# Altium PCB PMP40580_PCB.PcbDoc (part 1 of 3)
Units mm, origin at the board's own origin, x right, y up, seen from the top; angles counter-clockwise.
Board outline 215 x 165 mm, 2 copper layers (Top Layer, Bottom Layer), stack 1.575 mm thick; 235 components, 90 nets, 527 pads, 0 vias.
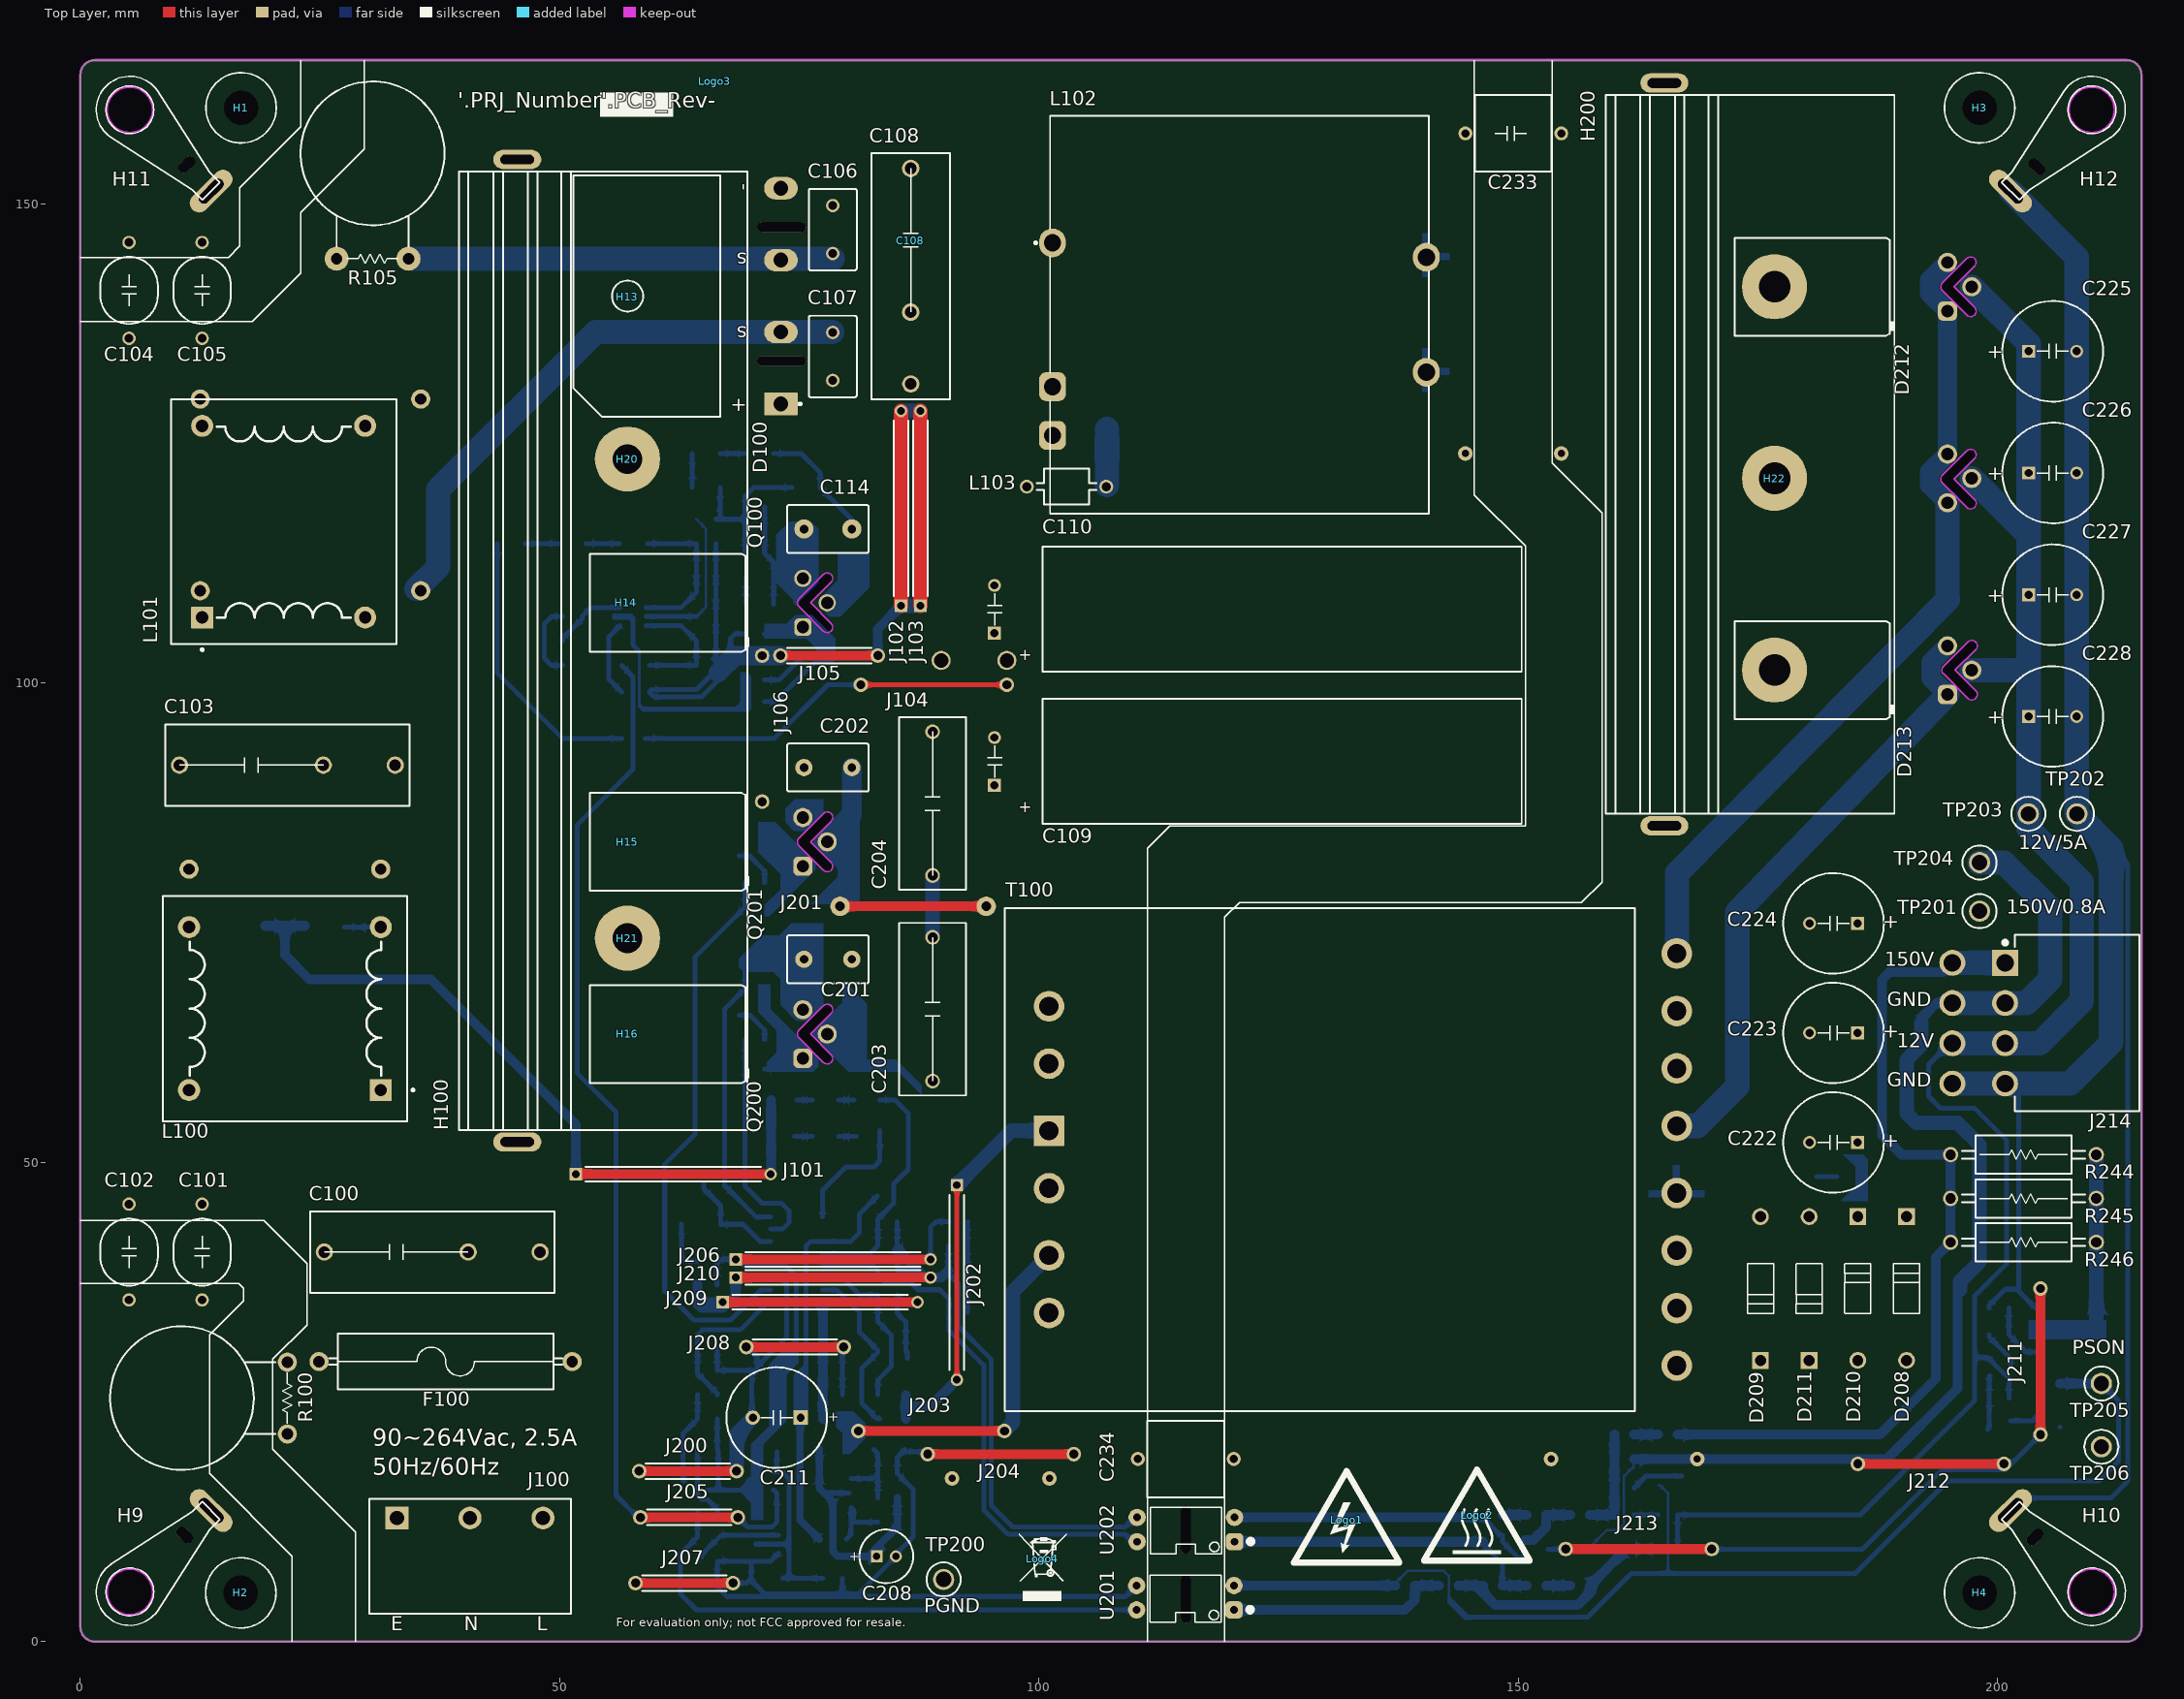
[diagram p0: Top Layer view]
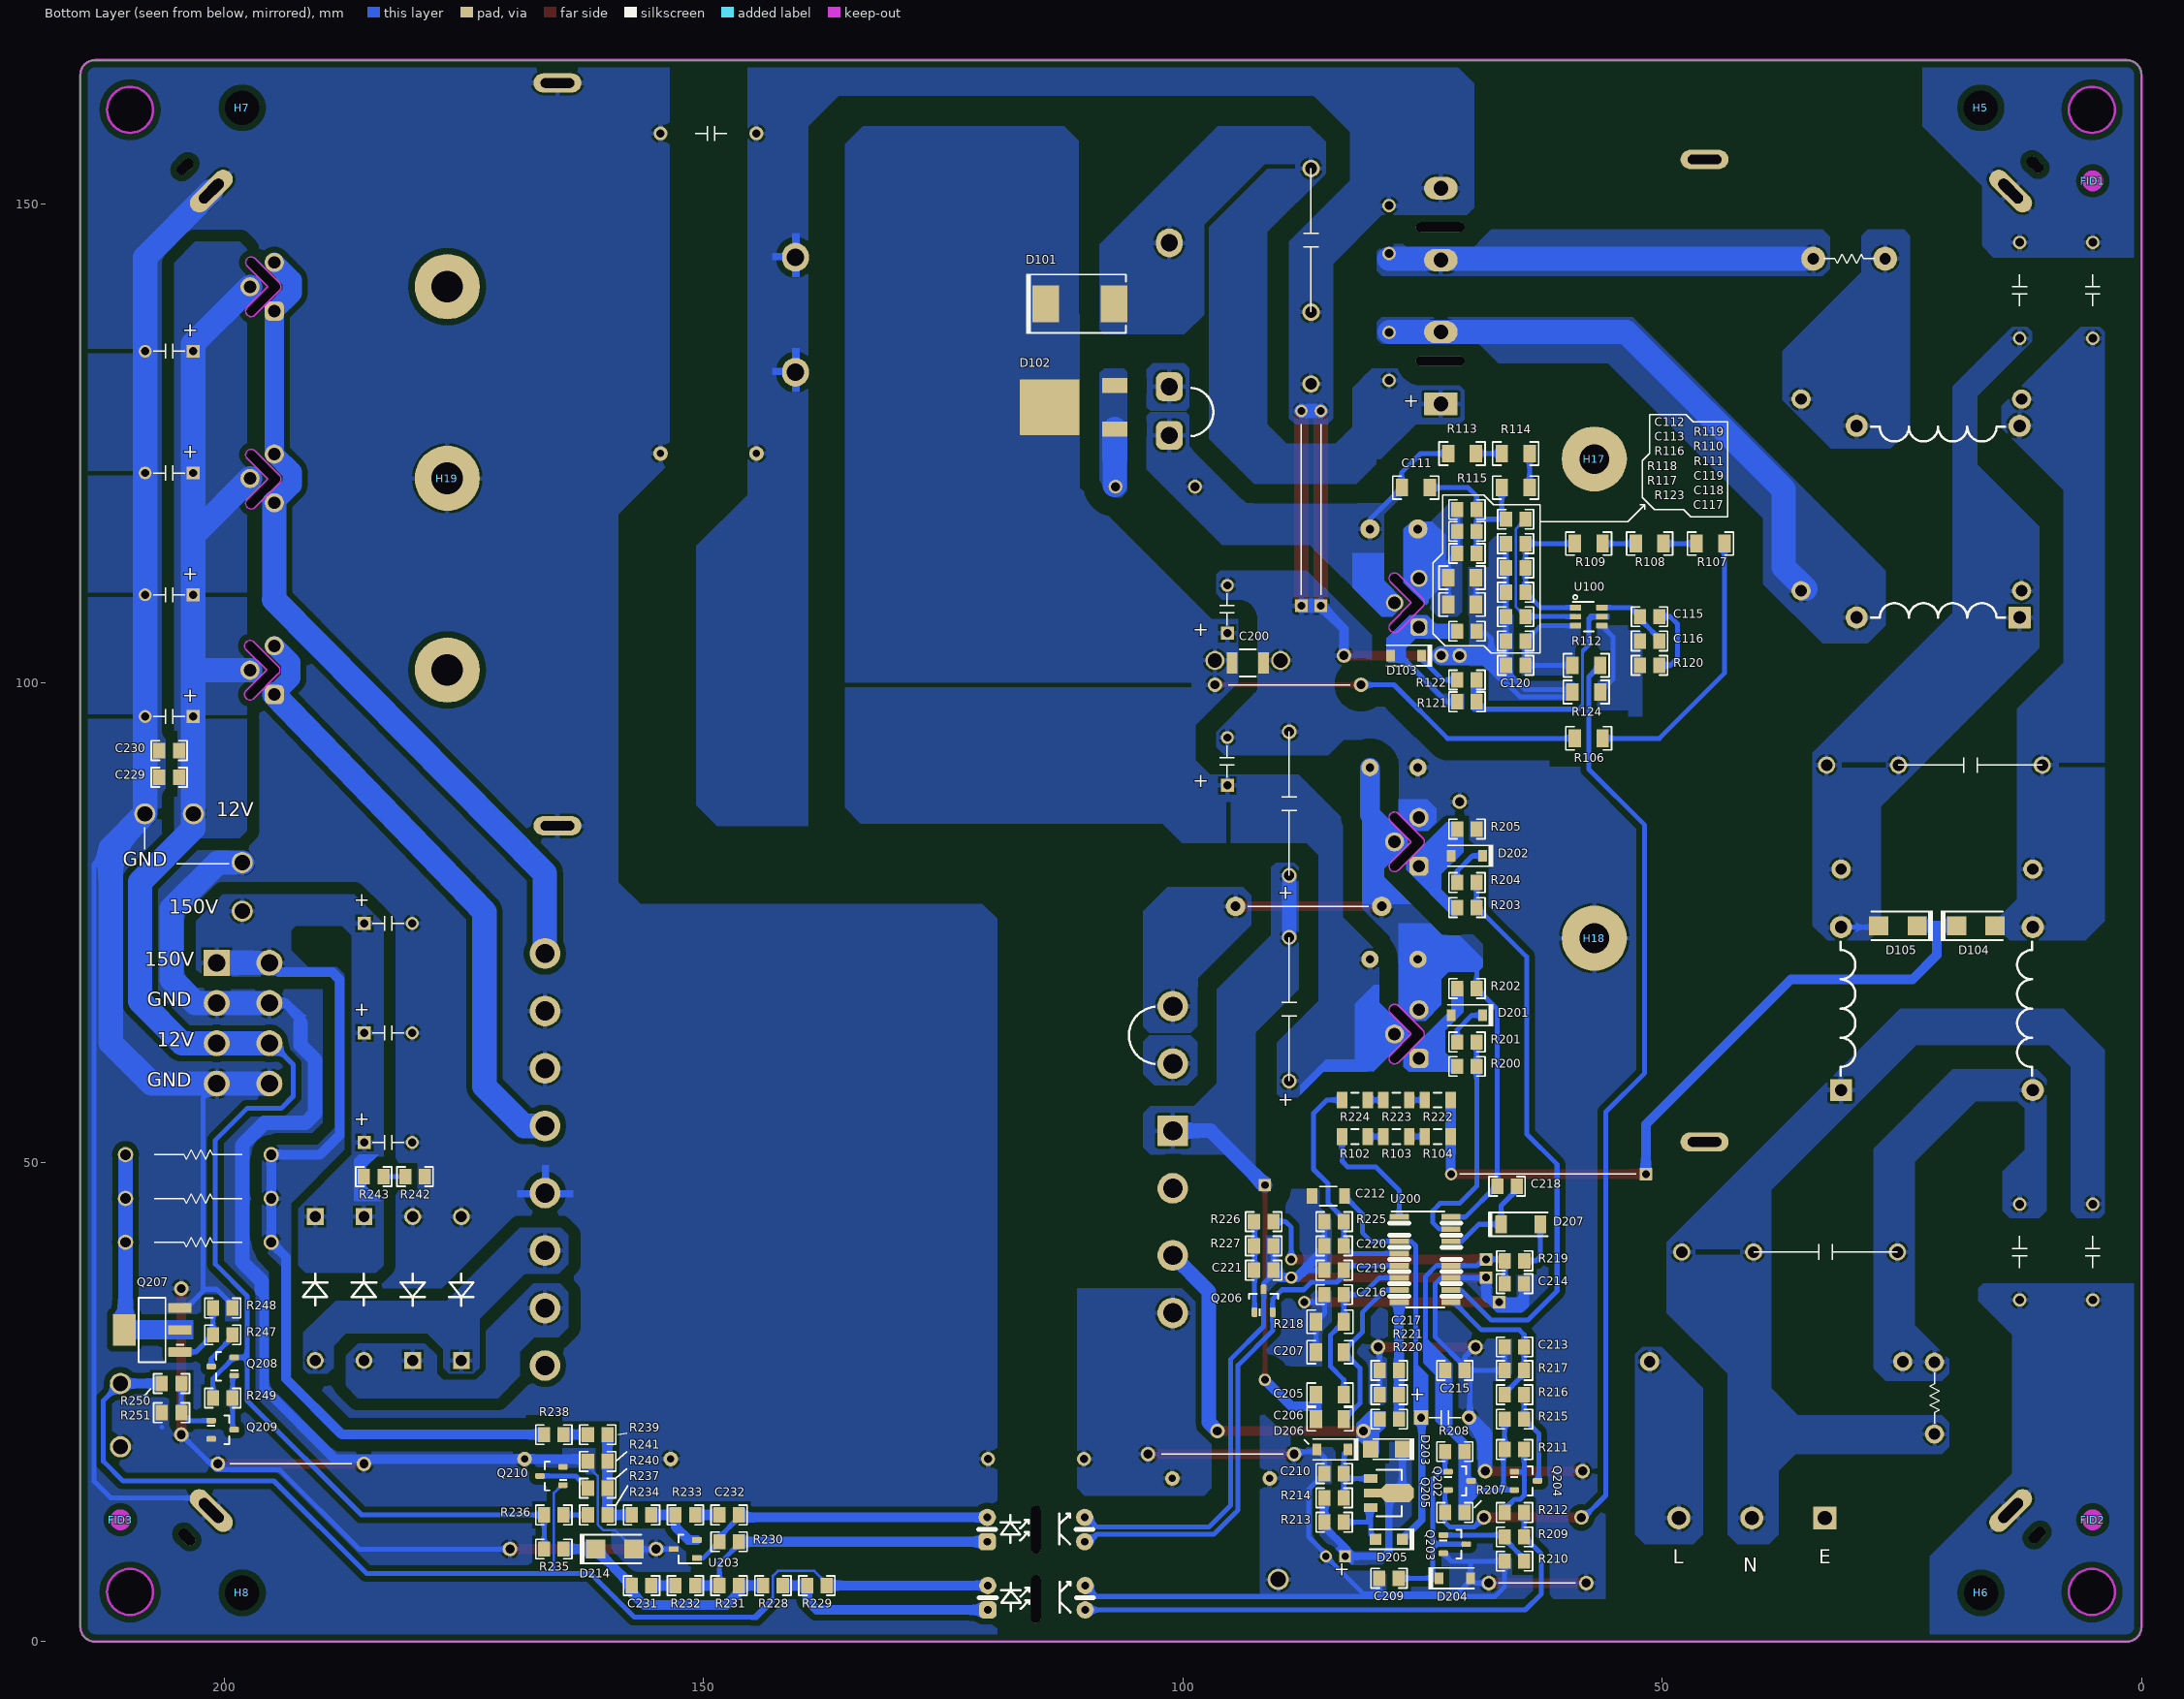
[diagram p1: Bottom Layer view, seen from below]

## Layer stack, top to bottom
Top Solder: solder mask 0.0102, Solder Resist, Dk 3.5
Top Layer: signal copper 0.0356
Dielectric1: core 1.5037, FR-4, Dk 4.8
Bottom Layer: signal copper 0.0356
Bottom Solder: solder mask 0.0102, Solder Resist, Dk 3.5

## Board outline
1.532,0 cw(c1.532,1.532) 0,1.532 0,163.468 cw(c1.532,163.468) 1.532,165 213.468,165 cw(c213.468,163.468) 215,163.468 215,1.532 cw(c213.468,1.532) 213.468,0
cut-out: 194.241,120.881 196.781,118.341 ccw(c197.185,118.745) 197.589,119.149 195.453,121.285 197.589,123.421 ccw(c197.185,123.825) 196.781,124.229 194.241,121.689 ccw(c194.645,121.285)
cut-out: 5.158,2.774 cw(c5.158,5.174) 2.758,5.174 cw(c5.158,5.174) 5.158,7.574 cw(c5.158,5.174) 7.558,5.174 cw(c5.158,5.174)
cut-out: 207.418,5.174 ccw(c209.818,5.174) 209.818,2.774 ccw(c209.818,5.174) 212.218,5.174 ccw(c209.818,5.174) 209.818,7.574 ccw(c209.818,5.174)
cut-out: 209.818,157.41 cw(c209.818,159.81) 207.418,159.81 cw(c209.818,159.81) 209.818,162.21 cw(c209.818,159.81) 212.218,159.81 cw(c209.818,159.81)
cut-out: 5.158,157.41 cw(c5.158,159.81) 2.758,159.81 cw(c5.158,159.81) 5.158,162.21 cw(c5.158,159.81) 7.558,159.81 cw(c5.158,159.81)
cut-out: 194.363,100.942 196.903,98.402 ccw(c197.307,98.806) 197.711,99.21 195.575,101.346 197.711,103.482 ccw(c197.307,103.886) 196.903,104.29 194.363,101.75 ccw(c194.767,101.346)
cut-out: 194.241,140.947 196.781,138.407 ccw(c197.185,138.811) 197.589,139.215 195.453,141.351 197.589,143.487 ccw(c197.185,143.891) 196.781,144.295 194.241,141.755 ccw(c194.645,141.351)
cut-out: 74.964,62.976 77.504,60.436 ccw(c77.908,60.84) 78.312,61.244 76.176,63.38 78.312,65.516 ccw(c77.908,65.92) 77.504,66.324 74.964,63.784 ccw(c75.368,63.38)
cut-out: 74.964,83.03 77.504,80.49 ccw(c77.908,80.894) 78.312,81.298 76.176,83.434 78.312,85.57 ccw(c77.908,85.974) 77.504,86.378 74.964,83.838 ccw(c75.368,83.434)
cut-out: 74.964,107.976 77.504,105.436 ccw(c77.908,105.84) 78.312,106.244 76.176,108.38 78.312,110.516 ccw(c77.908,110.92) 77.504,111.324 74.964,108.784 ccw(c75.368,108.38)

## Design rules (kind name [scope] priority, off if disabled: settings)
AcuteAngle [All] p1: minimum=4.50000000000000E+0001 checktracksonly=FALSE
AssemblyTestPointUsage [All] p1: valid=2
BoardOutlineClearance BoardOutlineClearance_MountingHoles [OnCopper and InComponentClass('Mounting Holes')] p1: gap=1.016 ignorepadtopadclearanceinfootprint=FALSE
BoardOutlineClearance BoardOutlineClearance_Poly [OnCopper and IsPoly] p2: gap=0.635 ignorepadtopadclearanceinfootprint=FALSE
BoardOutlineClearance [OnCopper and Not InComponentClass('Logo') and not InComponentClass('FiducialMark') and not InRegion(1000,500,4000,800) and not InPoly] p3: gap=1.905 ignorepadtopadclearanceinfootprint=FALSE
Clearance "Schematic Clearance Constraint_5" [InNet('150V')] p1: gap=1.27 ignorepadtopadclearanceinfootprint=FALSE
Clearance "Schematic Clearance Constraint_4" [InNet('ACIN')] p2: gap=2.032 ignorepadtopadclearanceinfootprint=FALSE
Clearance "Schematic Clearance Constraint_3" [InNet('HS')] p3: gap=2.032 ignorepadtopadclearanceinfootprint=FALSE
Clearance "Schematic Clearance Constraint_24" [InNet('PFC_DC+')] p4: gap=2.032 ignorepadtopadclearanceinfootprint=FALSE
Clearance "Schematic Clearance Constraint_23" [InNet('NetC203_2')] p5: gap=2.032 ignorepadtopadclearanceinfootprint=FALSE
Clearance "Schematic Clearance Constraint_22" [InNet('HO')] p6: gap=2.032 ignorepadtopadclearanceinfootprint=FALSE
Clearance "Schematic Clearance Constraint_21" [InNet('HB')] p7: gap=2.032 ignorepadtopadclearanceinfootprint=FALSE
Clearance "Schematic Clearance Constraint_18" [InNet('NetC100_1')] p8: gap=2.032 ignorepadtopadclearanceinfootprint=FALSE
Clearance "Schematic Clearance Constraint_17" [InNet('NetR108_1')] p9: gap=2.032 ignorepadtopadclearanceinfootprint=FALSE
Clearance "Schematic Clearance Constraint_16" [InNet('NetC106_2')] p10: gap=2.032 ignorepadtopadclearanceinfootprint=FALSE
Clearance "Schematic Clearance Constraint_15" [InNet('NetC103_1')] p11: gap=2.032 ignorepadtopadclearanceinfootprint=FALSE
Clearance "Schematic Clearance Constraint_14" [InNet('Neutral')] p12: gap=2.032 ignorepadtopadclearanceinfootprint=FALSE
Clearance "Schematic Clearance Constraint_13" [InNet('NetC107_1')] p13: gap=2.032 ignorepadtopadclearanceinfootprint=FALSE
Clearance "Schematic Clearance Constraint_12" [InNet('NetC103_2')] p14: gap=2.032 ignorepadtopadclearanceinfootprint=FALSE
Clearance "Schematic Clearance Constraint_11" [InNet('NetC107_2')] p15: gap=2.032 ignorepadtopadclearanceinfootprint=FALSE
Clearance "Schematic Clearance Constraint_10" [InNet('NetC111_1')] p16: gap=2.032 ignorepadtopadclearanceinfootprint=FALSE
Clearance "Schematic Clearance Constraint_9" [InNet('NetR107_1')] p17: gap=2.032 ignorepadtopadclearanceinfootprint=FALSE
Clearance "Schematic Clearance Constraint_8" [InNet('NetL101_3')] p18: gap=2.032 ignorepadtopadclearanceinfootprint=FALSE
Clearance "Schematic Clearance Constraint_7" [InNet('NetR113_1')] p19: gap=2.032 ignorepadtopadclearanceinfootprint=FALSE
Clearance "Schematic Clearance Constraint_6" [InNet('PFC_DC+')] p20: gap=2.032 ignorepadtopadclearanceinfootprint=FALSE
Clearance "Schematic Clearance Constraint_2" [InNet('NetR106_1')] p21: gap=2.032 ignorepadtopadclearanceinfootprint=FALSE
Clearance "Schematic Clearance Constraint_1" [InNet('Line')] p22: gap=2.032 ignorepadtopadclearanceinfootprint=FALSE
Clearance "Schematic Clearance Constraint" [InNet('NetR114_1')] p23: gap=2.032 ignorepadtopadclearanceinfootprint=FALSE
Clearance Clearance_Keepouts [((IsTrack Or IsArc) And Not InPoly) And IsFree and IsKeepOut vs ((IsTrack Or IsArc) And Not InPoly) And IsFree and IsKeepOut] p24 off: gap=0 ignorepadtopadclearanceinfootprint=FALSE
Clearance Clearance_Poly_SGND [InPolygon vs InNet('SGND')] p25: gap=1.27 ignorepadtopadclearanceinfootprint=FALSE
Clearance Clearance_Poly [InPolygon] p26: gap=0.635 ignorepadtopadclearanceinfootprint=FALSE
Clearance Clearance_FiducialMark [IsKeepOut and InComponentClass('FiducialMark') vs IsPad and InComponentClass('FiducialMark')] p27: gap=0 ignorepadtopadclearanceinfootprint=FALSE
Clearance [All] p28: gap=0.2 ignorepadtopadclearanceinfootprint=FALSE except(0: Arc-Hole Track-Hole SMDPad-Hole THPad-Hole Via-Hole Fill-Hole Poly-Hole Region-Hole Text-Hole)
ComponentClearance ComponentClearance_MountingHoles_FiducialMarks [InComponentClass('Mounting Holes') vs InComponentClass('FiducialMark')] p1: gap=1.27 collisioncheckmode=3 verticalgap=0.254 showdistances=FALSE
ComponentClearance ComponentClearance_Shunt [InComponentClass('Header') vs InComponentClass('Shunt')] p2: gap=0 collisioncheckmode=3 verticalgap=0 showdistances=FALSE
ComponentClearance ComponentClearance_Logo [InComponentClass('Logo')] p3: gap=1.27 collisioncheckmode=3 verticalgap=0.254 showdistances=FALSE
ComponentClearance ComponentClearance_ScrewToNut [(HasFootprint('NY PMS 440 0025 PH')) vs (HasFootprint('Keystone_1902C'))] p4: gap=0.127 collisioncheckmode=3 verticalgap=0.254 showdistances=FALSE
ComponentClearance ComponentClearance_MountingHoles [InComponentClass('Mounting Holes')] p5: gap=6.35 collisioncheckmode=3 verticalgap=2540 showdistances=FALSE
ComponentClearance ComponentClearance_SmallPassives [HasFootprint('0201*') or HasFootprint('0402*') or HasFootprint('0508') or HasFootprint('0603*') or HasFootprint('0612') or HasFootprint('0805*') or HasFootprint('0815*') or HasFootprint('0830*') or HasFootprint('1206*') or HasFootprint('1210*') or HasFootprint('1808*') or HasFootprint('1812*') or HasFootprint('1825*') or HasFootprint('2010*') or HasFootprint('2220*') or HasFootprint('2225*') or HasFootprint('2512*') or HasFootprint('2728*') or HasFootprint('3518*') vs HasFootprint('0201*') or HasFootprint('0402*') or HasFootprint('0508') or HasFootprint('0603*') or HasFootprint('0612') or HasFootprint('0805*') or HasFootprint('0815*') or HasFootprint('0830*') or HasFootprint('1206*') or HasFootprint('1210*') or HasFootprint('1808*') or HasFootprint('1812*') or HasFootprint('1825*') or HasFootprint('2010*') or HasFootprint('2220*') or HasFootprint('2225*') or HasFootprint('2512*') or HasFootprint('2728*') or HasFootprint('3518*')] p6: gap=0.38 collisioncheckmode=3 verticalgap=0.254 showdistances=FALSE
ComponentClearance ComponentClearance_THtoSMT [IsThruComponent vs IsSMTComponent] p7: gap=1.016 collisioncheckmode=3 verticalgap=0.762 showdistances=FALSE
ComponentClearance ComponentClearance_THtoTH [IsThruComponent vs IsThruComponent] p8: gap=0.762 collisioncheckmode=3 verticalgap=0.762 showdistances=FALSE
ComponentClearance [All] p9: gap=0.762 collisioncheckmode=3 verticalgap=0.254 showdistances=FALSE
DiffPairsRouting [All] p1: maxlimit=2.54 minlimit=0.254 mostfreqgap=0.254 toplayer_minwidth=0.381 toplayer_maxwidth=0.381 toplayer_prefwidth=0.381 bottomlayer_minwidth=0.381 bottomlayer_maxwidth=0.381 bottomlayer_prefwidth=0.381 maxuncoupledlength=25.4
FabricationTestPointUsage TestPointUsage [All] p1: valid=2 allowmultiple=FALSE
FabricationTestpoint Testpoint [All] p1: side=3 testpointundercomponent=TRUE minsize=1.016 maxsize=2.54 preferedsize=1.524 minholesize=0 maxholesize=1.016 preferedholesize=0.813 testpointgrid=0.025 allowsidetop=TRUE allowsidebottom=TRUE usegrid=TRUE gridtolerance=0
FanoutControl Fanout_LCC [IsLCC] p1: bgadir=Out bgaviamode=Centered fanoutstyle=Auto fanoutdirection=Alternating viagrid=0.025 // Fanout_LCC (Default Rule)
FanoutControl Fanout_BGA [IsBGA] p2: bgadir=Out bgaviamode=Centered fanoutstyle=Auto fanoutdirection=Alternating viagrid=0.025 // Fanout_BGA (Default Rule)
FanoutControl Fanout_Default [All] p4: bgadir=Out bgaviamode=Centered fanoutstyle=Auto fanoutdirection=Alternating viagrid=0.025 // Fanout_Default (Default Rule)
FanoutControl Fanout_Small [(CompPinCount < 5)] p5: bgadir=Out bgaviamode=Centered fanoutstyle=Auto fanoutdirection=OutThenIn viagrid=0.025 // Fanout_Small (Default Rule)
Height [All] p1: minheight=0 maxheight=25.5 prefheight=16
HoleSize [All] p1: absolutevalues=TRUE maxlimit=6.375 minlimit=0.2 maxpercent=80.000 minpercent=20.000
MinimumAnnularRing MinimumAnnularRing_ThermalPadVias [IsVia and InAnyComponent] p1: minimumring=0.15
MinimumAnnularRing [All] p2: minimumring=0.203
MinimumSolderMaskSliver MinimumSolderMaskSliver_Logo [InComponentClass('Logo') vs InComponentClass('Logo')] p1: minsoldermaskwidth=0.018
MinimumSolderMaskSliver [All] p2: minsoldermaskwidth=0.1
PlaneConnect [All] p1: planeconnectstyle=Relief reliefexpansion=0.254 reliefentries=4 reliefconductorwidth=0.254 reliefairgap=0.254
PolygonConnect [All] p1: thpad.connectstyle=Relief thpad.reliefconductorwidth=0.508 thpad.reliefentries=4 thpad.polygonreliefangle="90 Angle" thpad.airgapwidth=0.254 smdpad.connectstyle=Direct smdpad.reliefconductorwidth=0.254 smdpad.reliefentries=4 smdpad.polygonreliefangle="90 Angle" smdpad.airgapwidth=0.254 via.connectstyle=Direct via.reliefconductorwidth=0.254 via.reliefentries=4 via.polygonreliefangle="90 Angle" via.airgapwidth=0.254
RoutingLayers [All] p1: top layer_v5=FALSE bottom layer_v5=TRUE
RoutingVias ThermalPadVias [IsVia and InAnyComponent] p1: holewidth=0.2 width=0.5 viastyle="Through Hole" minholewidth=0.2 minwidth=0.5 maxholewidth=0.33 maxwidth=0.6
RoutingVias [All] p2: holewidth=0.406 width=0.864 viastyle="Through Hole" minholewidth=0.2 minwidth=0.66 maxholewidth=1.016 maxwidth=1.651
SilkToBoardRegionClearance [Not ((IsComment or IsDesignator) And (Hide <> 'False')) and not InRegion(1000,500,4000,800)] p1:
SilkToSilkClearance SilkToSilkClearance_Pb-FreeLogo [(HasFootprint('Pb-Free_Overlay_Medium') OR HasFootprint('Pb-Free_Overlay_Small')) vs (HasFootprint('Pb-Free_Overlay_Medium') OR HasFootprint('Pb-Free_Overlay_Small'))] p1: silktosilkclearance=0
SilkToSilkClearance [All] p2: silktosilkclearance=0.102
SilkToSolderMaskClearance SilkToComponentPadClearance [(IsPad or IsFill or IsRegion) and InAnycomponent] p1: minsilkscreentomaskgap=0.127 clearancetoexposedcopper=TRUE
SilkToSolderMaskClearance "Silk to Solder Mask Opening" [All] p2: minsilkscreentomaskgap=0.102 clearancetoexposedcopper=FALSE
SolderMaskExpansion [All] p1: expansion=0.05
Width [All] p1: maxlimit=2.54 minlimit=0.152 preferedwidth=0.254 checkconnectedcopper=TRUE
13 further rules are at their usual default settings.

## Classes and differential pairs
component class FiducialMark: FID1 FID2 FID3
component class PMP40580_PFC: C100 C101 C102 C103 C104 C105 C106 C107 C108 C109 C110 C111 C112 C113 C114 C115 C116 C117 C118 C119 C120 D100 D101 D102 D103 D104 D105 F100 FID1 FID2 FID3 H1 H2 H3 H4 H5 H6 H7 H8 H9 H10 H11 H12 H13 H14 H15 H16 H17 H18 H19 H20 H21 H22 H100 J100 J101 J102 J103 J104 J105 J106 J? L100 L101 L102 L103 Logo1 Logo2 Logo3 Logo4 Q100 R100 R102 R103 R104 R105 R106 R107 R108 R109 R110 R111 R112 R113 R114 R115 R116 R117 R118 R119 R120 R121 R122 R123 R124 U100
component class PMP40580_LLC: C200 C201 C202 C203 C204 C205 C206 C207 C208 C209 C210 C211 C212 C213 C214 C215 C216 C217 C218 C219 C220 C221 C222 C223 C224 C225 C226 C227 C228 C229 C230 C231 C232 C233 C234 D201 D202 D203 D204 D205 D206 D207 D208 D209 D210 D211 D212 D213 D214 H200 J200 J201 J202 J203 J204 J205 J206 J207 J208 J209 J210 J211 J212 J213 J214 Q200 Q201 Q202 Q203 Q204 Q205 Q206 Q207 Q208 Q209 Q210 R200 R201 R202 R203 R204 R205 R207 R208 R209 R210 R211 R212 R213 R214 R215 R216 R217 R218 R219 R220 R221 R222 R223 R224 R225 R226 R227 R228 R229 R230 R231 R232 R233 R234 R235 R236 R237 R238 R239 R240 R241 R242 R243 R244 R245 R246 R247 R248 R249 R250 R251 T1 T100 TP200 TP201 TP202 TP203 TP204 TP205 TP206 U200 U201 U202 U203
component class Screw: H13 H14 H15 H16

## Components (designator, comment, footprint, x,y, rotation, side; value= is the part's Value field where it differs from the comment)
C100 "ECQ-UAAF474M" CAPRR2250W80L2550T850H1750 36.703,40.64 r0 top value=0.47µF
C101 "CD45-E2GA102M-NKA" CD45_700X600X1100 12.7,40.64 r270 top value=1000pF
C102 "CD45-E2GA102M-NKA" CD45_700X600X1100 5.08,40.64 r270 top value=1000pF
C103 "ECQ-UAAF474M" CAPRR2250W80L2550T850H1750 21.59,91.44 r0 top value=0.47µF
C104 "CD45-E2GA102M-NKA" CD45_700X600X1100 5.08,140.97 r270 top value=1000pF
C105 "CD45-E2GA102M-NKA" CD45_700X600X1100 12.7,140.97 r90 top value=1000pF
C106 "CC45SL3AD221JYNNA" CC45_850x500x1250#1 78.486,147.32 r270 top value=220pF
C107 "CC45SL3AD221JYNNA" CC45_850x500x1250#1 78.486,134.08 r270 top value=220pF
C108 "ECQ-E2W155KH" ECQE_2570x820x1720 86.626,142.462 r270 top value=1.5uF
C108 "=PartNumber" MPK_1800x950 86.614,146.177 r270 top value=1uF
C109 "450BXW68MEFC12.5X45" BXW_1250X5000_HORIZONTAL_DOWN 97.657,91.821 r90 top value=68uF
C110 "450BXW68MEFC12.5X45" BXW_1250X5000_HORIZONTAL_DOWN 97.657,107.696 r90 top value=68uF
C111 "VJ1206A100JXGAT5Z" 1206 75.692,120.396 r180 bottom value=10pF
C112 "GRM2165C1H332JA01D" 0805_HV 70.358,118.11 r0 bottom value=3300pF
C113 "08055A471JAT2A" 0805_HV 70.358,115.824 r0 bottom value=470pF
C114 "CC45SL3AD221JYNNA" CC45_850x500x1250#2 77.978,116.078 r0 top value=220pF
C115 "GRM21BR71E184KA01L" 0805_HV 51.308,106.934 r180 bottom value=0.18uF
C116 "GRM219R71E473KA01D" 0805_HV 51.308,104.394 r0 bottom value=0.047uF
C117 "GRM21BR71H474KA88L" 0805_HV 65.278,104.394 r0 bottom value=0.47uF
C118 "08055A100JAT2A" 0805_HV 65.278,106.934 r0 bottom value=10pF
C119 "GRM2165C1H222JA01D" 0805_HV 65.278,109.474 r0 bottom value=2200pF
C120 "GRM21BZ71E106KE15L" 0805_HV 65.278,101.854 r0 bottom value=10uF
C200 "C1210C104KBRAC7800" 1210_280 93.218,102.108 r0 bottom value=0.1uF
C201 "CC45SL3AD221JYNNA" CC45_850x500x1250#3 77.978,71.184 r0 top value=220pF
C202 "CC45SL3AD221JYNNA" CC45_850x500x1250#3 77.978,91.186 r0 top value=220pF
C203 "B32642B0153J" B32652_1800x700x1250 88.9,65.977 r90 top value=15nF
C204 "B32642B0153J" B32652_1800x700x1250 88.9,87.424 r90 top value=15nF
C205 "GRM31A5C2J151JW01D" 1206 84.65,25.75 r180 bottom value=150pF
C206 "12067A680JAT2A" 1206 84.65,23.21 r180 bottom value=68pF
C207 "GRM3195C1H822JA01D" 1206 84.65,30.195 r0 bottom value=8200pF
C208 "EKZE500ELL220ME11D" Chemi-Con_500x1100 84.074,8.89 r0 top value=22uF
C209 "08055C104JAT2A" 0805_HV 78.486,6.604 r0 bottom value=0.1uF
C210 "08055C104JAT2A" 0805_HV 84.201,17.526 r0 bottom value=0.1uF
C211 "UVR1V331MPD" VR_1000x1250 72.644,23.368 r180 top value=330uF
C212 "C3216X7S2A225K160AB" 1206_180 84.836,46.482 r180 bottom value=2.2uF
C213 "C0805C683K1RACTU" 0805_HV 65.405,30.734 r0 bottom value=0.068uF
C214 "GRM21BR71E475KA73L" 0805_HV 65.405,37.338 r180 bottom value=4.7uF
C215 "GRM21BR71E475KA73L" 0805_HV 71.628,28.29 r180 bottom value=4.7uF
C216 "GRM2165C1H101JA01D" 0805_HV 84.201,36.195 r0 bottom value=100pF
C217 "C0805C100J5GACTU" 0805_HV 78.466,28.29 r0 bottom value=10pF
C218 "GRM219R71C225KE15" 0805_HV 66.182,47.498 r0 bottom value=2.2uF
C219 "GRM216R71E471KA01D" 0805_HV 84.201,38.735 r0 bottom value=470pF
C220 "C0805C104K3RACTU" 0805_HV 84.201,41.275 r0 bottom value=0.1uF
C221 "GRM216R71E471KA01D" 0805_HV 91.567,38.735 r180 bottom value=470pF
C222 "EKXG401ELL6R8MJ16S" CHEMI-CON_1000X1600 182.88,52.07 r180 top value=6.8uF
C223 "EKXG401ELL6R8MJ16S" CHEMI-CON_1000X1600 182.88,63.5 r180 top value=6.8uF
C224 "EKXG401ELL6R8MJ16S" CHEMI-CON_1000X1600 182.88,74.93 r180 top value=6.8uF
C225 "ELXZ250ELL471MJ16S" CHEMI-CON_1000X1600 205.74,134.62 r0 top value=470uF
C226 "ELXZ250ELL471MJ16S" CHEMI-CON_1000X1600 205.74,121.92 r0 top value=470uF
C227 "ELXZ250ELL471MJ16S" CHEMI-CON_1000X1600 205.74,109.22 r0 top value=470uF
C228 "ELXZ250ELL471MJ16S" CHEMI-CON_1000X1600 205.74,96.52 r0 top value=470uF
C229 "GRM21BC71E106KE11L" 0805_HV 205.74,90.17 r0 bottom value=10uF
C230 "GRM21BR71E104KA01L" 0805_HV 205.74,92.964 r0 bottom value=0.1uF
C231 "08055C332KAT2A" 0805_HV 156.464,5.842 r180 bottom value=3300pF
C232 "C0805C103K1RACTU" 0805_HV 147.32,13.208 r180 bottom value=0.01uF
C233 "" DE_800x1200x800 149.479,157.353 r0 top value=1000pF
C234 "" DE_800x1200x800 115.316,19.05 r0 top value=1000pF
D100 "TS15P05G" FP-KBJ608G_BENT 59.076,140.38 r180 top value=600V
D101 "MURS360T3G" SMC 110.744,139.573 r180 bottom value=600V
D102 "MURHD560T4G" DPAK 110.49,128.778 r0 bottom value=600V
D103 "1N4148W-7-F" SOD-123 76.708,102.87 r0 bottom value=100V
D104 "MURA160T3G" SMA 17.272,74.676 r180 bottom value=600V
D105 "MURA160T3G" SMA 25.4,74.676 r0 bottom value=600V
D201 "1N4148W-7-F" SOD-123 70.358,65.342 r0 bottom value=100V
D202 "1N4148W-7-F" SOD-123 70.358,81.979 r0 bottom value=100V
D203 "PMEG10020ELRX" SOD-123W 78.486,20.066 r0 bottom value=100V
D204 "MMSZ4699T1G" SOD-123 71.628,6.604 r180 bottom value=12V
D205 "PMEG6010CEH,115" SOD-123F 78.486,10.668 r0 bottom value=60V
D206 "BZT52C15-7-F" SOD-123 84.396,20.041 r0 bottom value=15V
D207 "ES1JAF" SMAF 64.75,43.53 r180 bottom value=600V
D208 "STTH1R02" DO-41_15mm 190.5,36.83 r270 top value=200V
D209 "STTH1R02" DO-41_15mm 175.26,36.83 r90 top value=200V
D210 "STTH1R02" DO-41_15mm 185.42,36.83 r270 top value=200V
D211 "STTH1R02" DO-41_15mm 180.34,36.83 r90 top value=200V
D212 "STPS40L45CT" TO-220FP_HORIZONTAL_100MIL_STANDOFF2300 194.767,141.351 r90 top value=45V
D213 "STPS40L45CT" TO-220FP_HORIZONTAL_100MIL_STANDOFF2300 194.767,101.346 r90 top value=45V
D214 "1SMA5926BT3G" SMA 159.258,9.652 r180 bottom value=11V
F100 "02153.15MXEP" FUSE_215 38.1,29.21 r0 top
FID1 "Fiducial" Fiducial10-20 5.08,152.4 r180 bottom
FID2 "Fiducial" Fiducial10-20 5.08,12.7 r180 bottom
FID3 "Fiducial" Fiducial10-20 210.82,12.7 r180 bottom
H1 "4820" KEYSTONE_4820 16.764,160.02 r0 top locked
H2 "4820" KEYSTONE_4820 16.737,5.08 r0 top locked
H3 "4820" KEYSTONE_4820 198.12,160.02 r0 top locked
H4 "4820" KEYSTONE_4820 198.12,5.08 r0 top locked
H5 "1903C" KEYSTONE_1903C 16.764,160.02 r180 bottom locked
H6 "1903C" KEYSTONE_1903C 16.737,5.08 r180 bottom locked
H7 "1903C" KEYSTONE_1903C 198.12,160.02 r180 bottom locked
H8 "1903C" KEYSTONE_1903C 198.12,5.08 r180 bottom locked
H9 "" "GND CONNECT" 5.156,5.182 r45 top
H10 "" "GND CONNECT" 209.829,5.182 r135 top
H11 "" "GND CONNECT" 5.156,159.817 r315 top
H12 "" "GND CONNECT" 209.829,159.817 r225 top
H13 "MPMS 003 0005 PH" BuildingFastener_MPMS_003_0005_PH 57.076,140.3 r90 top
H14 "MPMS 003 0005 PH" BuildingFastener_MPMS_003_0005_PH 56.935,108.38 r90 top
H15 "MPMS 003 0005 PH" BuildingFastener_MPMS_003_0005_PH 57.076,83.4 r90 top
H16 "MPMS 003 0005 PH" BuildingFastener_MPMS_003_0005_PH 57.076,63.4 r90 top
H17 "RM3X8MM 2701" "APM_RM3X8MM 2701" 57.076,123.38 r90 bottom
H18 "RM3X8MM 2701" "APM_RM3X8MM 2701" 57.076,73.38 r90 bottom
H19 "RM3X8MM 2701" "APM_RM3X8MM 2701" 176.73,121.36 r180 bottom
H20 "9080032809" 9080032809 57.076,123.38 r90 top
H21 "9080032809" 9080032809 57.076,73.38 r90 top
H22 "9080032809" 9080032809 176.73,121.36 r0 top
H100 "SK443100SA" SK-443-AL-100 69.576,53.38 r90 top locked
H200 "SK44375SA" SK-443-AL-75 189.23,86.36 r90 top
J100 "PartNumber" 691312410003 40.64,8.89 r0 top
J101 "923345-08-C" FP-923345-08-C_JUMPER2-MFG 61.849,48.768 r0 top
J102 "923345-08-C" FP-923345-08-C_JUMPER2-MFG 85.598,118.228 r90 top
J103 "923345-08-C" FP-923345-08-C_JUMPER2-MFG 87.63,118.228 r90 top
J104 "923345-06-C" CONN_923345-06-C#1 89.027,99.822 r0 top
J105 "923345-04-C" 3M_923345-04-C 78.105,102.87 r180 top
J106 "923345-06-C" CONN_923345-06-C#1 71.12,95.25 r90 top
J200 "923345-04-C" 3M_923345-04-C 63.373,17.78 r0 top
J201 "923345-06-C" CONN_923345-06-C#2 86.868,76.708 r0 top
J202 "923345-08-C" FP-923345-08-C_JUMPER2-MFG 91.44,37.465 r270 top
J203 "923345-06-C" CONN_923345-06-C#1 88.773,21.971 r0 top
J204 "923345-06-C" CONN_923345-06-C#1 96.012,19.558 r0 top
J205 "923345-04-C" 3M_923345-04-C 63.5,12.954 r0 top
J206 "923345-08-C" FP-923345-08-C_JUMPER2-MFG 78.519,39.878 r0 top
J207 "923345-04-C" 3M_923345-04-C 62.992,6.096 r0 top locked
J208 "923345-04-C" 3M_923345-04-C 74.549,30.734 r0 top
J209 "923345-08-C" FP-923345-08-C_JUMPER2-MFG 77.169,35.407 r0 top
J210 "923345-08-C" FP-923345-08-C_JUMPER2-MFG 78.519,37.973 r0 top
J211 "923345-06-C" CONN_923345-06-C#1 204.47,29.21 r90 top
J212 "923345-06-C" CONN_923345-06-C#1 193.04,18.542 r0 top
J213 "923345-06-C" CONN_923345-06-C#1 162.56,9.652 r180 top
J214 "64900829522" 64900829522 208.28,64.516 r90 top
L100 "JLB20213" JLB20213 21.336,66.04 r180 top value=20mH
L101 "JLB20213" JLB20213 21.209,116.84 r90 top value=20mH
L102 "JLC42184" JLC42178 120.904,138.43 r0 top
L103 "28L0138-10R-10" 28L0138 102.87,120.498 r0 top value="75 ohm"
Logo1 "DANGER HIGH VOLTAGE" IEC_HighVoltage_Medium 132.08,12.7 r0 top (schematic designator LOGO1)
Logo2 "CAUTION HOT SURFACE" IEC_HotSurface_Medium 145.674,13.19 r0 top (schematic designator LOGO2)
Logo3 "FCC disclaimer" FCC_disclaimer 66.167,162.814 r0 top
Logo4 "WEEE logo" WEEE_Minimum 100.33,8.636 r0 top
Q100 "STF24N60DM2" TO-220FP_Horizontal_100mil_Standoff2300 75.368,108.38 r90 top value=600V
Q200 "IPA65R190CFD" TO-220FP_HORIZONTAL_100MIL_STANDOFF2300 75.368,63.38 r90 top value=650V
Q201 "IPA65R190CFD" TO-220FP_HORIZONTAL_100MIL_STANDOFF2300 75.368,83.434 r90 top value=650V
Q202 "MMBT3904" SOT-23 71.12,16.764 r180 bottom value="40 V"
Q203 "MMBT3904" SOT-23 71.628,10.16 r180 bottom value="40 V"
Q204 "BC856B-7-F" SOT-23 64.205,16.764 r180 bottom value="65 V"
Q205 "BCX56-16,115" SOT-89-3 78.486,15.494 r180 bottom value="80 V"
Q206 "MMBT2907A" SOT-23 91.567,35.56 r90 bottom value="60 V"
Q207 "STN1NK60Z" SOT-223 207.518,32.512 r0 bottom value=600V
Q208 "MMBT2907A" SOT-23 200.152,28.702 r0 bottom value="60 V"
Q209 "MMBT3904" SOT-23 200.152,22.098 r180 bottom value="40 V"
Q210 "2N7002K-T1-E3" SOT-23 165.862,17.272 r0 bottom value=60V
R100 "V300LA2P" "S237 - Horizontal_Down"#1 21.59,25.4 r90 top
R102 "CRCW12061K65FKEA" 1206L 82.042,52.689 r180 bottom value=1.65k
R103 "CRCW12061K65FKEA" 1206L 77.724,52.689 r180 bottom value=1.65k
R104 "CRCW12061K65FKEA" 1206L 73.406,52.689 r180 bottom value=1.65k
R105 "B57237S0479M000" "S237 - Horizontal_Down"#2 30.48,144.272 r0 top value="4.70 ohm"
R106 "CRCW120651R0JNEA" 1206 57.658,94.234 r0 bottom value=51
R107 "CRCW12063M32FKEA" 1206 44.958,114.554 r180 bottom value=3.32Meg
R108 "CRCW12063M32FKEA" 1206 51.308,114.554 r180 bottom value=3.32Meg
R109 "CRCW12063M32FKEA" 1206 57.658,114.554 r180 bottom value=3.32Meg
R110 "CRCW0805110KFKEA" 0805_HV 65.278,114.554 r180 bottom value=110k
R111 "CRCW0805154KFKEA" 0805_HV 65.278,112.014 r180 bottom value=154k
R112 "CRCW120610R0FKEA" 1206 57.912,101.854 r180 bottom value=10.0
R113 "CRCW12063M32FKEA" 1206 70.866,123.952 r0 bottom value=3.32Meg
R114 "CRCW12063M32FKEA" 1206 65.278,123.952 r0 bottom value=3.32Meg
R115 "CRCW12063M32FKEA" 1206 65.278,120.396 r180 bottom value=3.32Meg
R116 "ERJ-6ENF2492V" 0805_HV 70.358,113.538 r180 bottom value=24.9k
R117 "ERJ-8RSJR12V" 1206 70.866,108.204 r0 bottom value=0.12
R118 "ERJ-8RSJR12V" 1206 70.866,110.998 r0 bottom value=0.12
R119 "CRCW08053K00JNEA" 0805_HV 65.278,117.094 r0 bottom value=3.0k
R120 "CRCW0805270KJNEA" 0805_HV 51.308,101.854 r180 bottom value=270k
R121 "CRCW080547R0JNEA" 0805_HV 70.358,98.044 r0 bottom value=47
R122 "CRCW080522R0JNEA" 0805_HV 70.358,100.33 r0 bottom value=22
R123 "CRCW080582K5FKEA" 0805_HV 70.358,105.41 r0 bottom value=82.5k
R124 "CRCW12060000Z0EA" 1206 57.912,99.06 r0 bottom value=0
R200 "CRCW080547R0JNEA" 0805_HV 70.358,60.008 r0 bottom value=47
R201 "CRCW080522R0JNEA" 0805_HV 70.358,62.548 r0 bottom value=22
R202 "CRCW080551K0JNEA" 0805_HV 70.358,68.136 r0 bottom value=51k
R203 "CRCW080547R0JNEA" 0805_HV 70.358,76.581 r0 bottom value=47
R204 "CRCW080522R0JNEA" 0805_HV 70.358,79.185 r0 bottom value=22
R205 "CRCW080551K0JNEA" 0805_HV 70.358,84.773 r0 bottom value=51k
R207 "CRCW08050000Z0EA" 0805_HV 71.628,13.462 r0 bottom value=0
R208 "CRCW08052K00JNEA" 0805_HV 71.628,19.812 r180 bottom value=2.0k
R209 "CRCW080510K0JNEA" 0805_HV 65.405,10.922 r180 bottom value=10k
R210 "CRCW0805100KJNEA" 0805_HV 65.405,8.382 r180 bottom value=100k
R211 "CRCW0805100KJNEA" 0805_HV 65.405,20.028 r0 bottom value=100k
R212 "CRCW080510K0JNEA" 0805_HV 65.405,13.462 r180 bottom value=10k
R213 "CRCW08050000Z0EA" 0805_HV 84.201,12.446 r0 bottom value=0
R214 "CRCW08052K00JNEA" 0805_HV 84.201,14.986 r0 bottom value=2.0k
R215 "CRCW08050000Z0EA" 0805_HV 65.405,23.21 r0 bottom value=0
R216 "CRCW0805866KFKEA" 0805_HV 65.405,25.75 r180 bottom value=866k
R217 "CRCW0805750KFKEA" 0805_HV 65.405,28.29 r180 bottom value=750k
R218 "CRCW1206133RFKEA" 1206 84.65,33.37 r180 bottom value=133
R219 "CRCW08052R20JNEA" 0805_HV 65.385,39.72 r180 bottom value=2.2
R220 "CRCW080544K2FKEA" 0805_HV 78.466,23.21 r0 bottom value=44.2k
R221 "CRCW08058K06FKEA" 0805_HV 78.466,25.75 r180 bottom value=8.06k
R222 "CRCW12064M99FKEA" 1206L 73.406,56.499 r180 bottom value=4.99Meg
R223 "CRCW12064M99FKEA" 1206L 77.724,56.499 r180 bottom value=4.99Meg
R224 "CRCW12064M99FKEA" 1206L 82.042,56.499 r180 bottom value=4.99Meg
R225 "CRCW0805300KJNEA" 0805_HV 84.201,43.815 r180 bottom value=300k
R226 "CRCW0805100KJNEA" 0805_HV 91.567,43.815 r0 bottom value=100k
R227 "CRCW080510K0JNEA" 0805_HV 91.567,41.275 r180 bottom value=10k
R228 "CRCW080510K0JNEA" 0805_HV 142.748,5.842 r0 bottom value=10k
R229 "CRCW080510K0JNEA" 0805_HV 138.176,5.842 r0 bottom value=10k
R230 "CRCW08053K01FKEA" 0805_HV 147.32,10.414 r0 bottom value=3.01k
R231 "CRCW08056K04FKEA" 0805_HV 147.32,5.842 r180 bottom value=6.04k
R232 "CRCW0805330RJNEA" 0805_HV 151.892,5.842 r0 bottom value=330
R233 "CRCW080533K2FKEA" 0805_HV 151.892,13.208 r0 bottom value=33.2k
R234 "CRCW08050000Z0EA" 0805_HV 156.464,13.208 r0 bottom value=0
R235 "CRCW08053K01FKEA" 0805_HV 165.608,9.652 r0 bottom value=3.01k
R236 "CRCW080510R0JNEA" 0805_HV 165.608,13.208 r0 bottom value=10
R237 "CRCW0805147KFKEA" 0805_HV 161.036,13.208 r0 bottom value=147k
R238 "CRCW0805499KFKEA" 0805_HV 165.608,21.59 r0 bottom value=499k
R239 "CRCW0805499KFKEA" 0805_HV 161.036,21.59 r0 bottom value=499k
R240 "CRCW080580K6FKEA" 0805_HV 161.036,16.002 r180 bottom value=80.6k
R241 "CRCW080521K5FKEA" 0805_HV 161.036,18.796 r180 bottom value=21.5k
R242 "ERJ-6GEYJ335V" 0805_HV 180.086,48.514 r0 bottom value=3.3Meg
R243 "ERJ-6GEYJ335V" 0805_HV 184.404,48.514 r0 bottom value=3.3Meg
R244 "PR02000201003JR500" PR02 202.692,50.8 r180 top value=100k
R245 "PR02000201003JR500" PR02 202.692,46.228 r180 top value=100k
R246 "PR02000201003JR500" PR02 202.692,41.656 r180 top value=100k
R247 "CRCW080522R0JNEA" 0805_HV 200.152,32.004 r0 bottom value=22
R248 "CRCW080510K0JNEA" 0805_HV 200.152,34.798 r0 bottom value=10k
R249 "CRCW080510K0JNEA" 0805_HV 200.152,25.4 r0 bottom value=10k
R250 "CRCW08054K70JNEA" 0805_HV 205.486,26.924 r0 bottom value=4.7k
R251 "CRCW080520K0JNEA" 0805_HV 205.486,23.876 r180 bottom value=20k
T100 "BCK-50-722D" EE49-8-20 129.286,50.292 r0 top locked value=400uH
TP200 "5011" Keystone5011 90.043,6.477 r180 top value=Black
TP201 "5010" Keystone5010 198.12,76.2 r90 top value=Red
TP202 "5011" Keystone5011 208.28,86.36 r90 top value=Black
TP203 "5010" Keystone5010 203.2,86.36 r90 top value=Red
TP204 "5011" Keystone5011 198.12,81.28 r90 top value=Black
TP205 "5010" Keystone5010 210.82,26.924 r90 top value=Red
TP206 "5011" Keystone5011 210.82,20.32 r90 top value=Black
U100 "UCC28056DBV" DBV0006A_N 57.658,106.934 r180 bottom
U200 "UCC256440-4DDBR" DDB0014A 74.723,39.852 r180 bottom
U201 "VO618A" DIP4-P-10.0-2.54 115.262,4.572 r180 top
U202 "VO618A" DIP4-P-10.0-2.54 115.316,11.684 r180 top
U203 "TL431AIDBZR" DBZ0003A_N 151.892,9.652 r0 bottom

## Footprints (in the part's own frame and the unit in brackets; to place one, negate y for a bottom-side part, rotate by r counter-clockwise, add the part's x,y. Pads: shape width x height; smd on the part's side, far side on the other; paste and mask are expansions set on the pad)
3M_923345-04-C [mil] "Jumper Wire, 400 mil Spacing, Yellow, Pkg of 200"
  round 60 hole 38: 1(-200,0) 2(200,0)
  silkscreen extent -173,-31 173,31, body extent -215,-30 215,30, height 80
28L0138 [mm] "TH, 2-Leads, Dia 3.51mm"
  round 1.45 hole 0.95: 1(-4.145,0) 2(4.145,0)
  silkscreen extent -3.11,-1.88 3.11,1.88, body extent -4.49,-1.88 4.49,1.88, height 3.76
0805_HV [mil] "0805 with 30mil clearance between pads"
  rect 50x63 smd: 1(-40,0) 2(40,0)
  silkscreen extent -74,-40 74,40, body extent -43,-29 43,29, height 57
1206 [mm] "1206 from SM-752 data"
  rect 1.3x1.85 smd: 1(-1.45,0) 2(1.45,0)
  silkscreen extent -2.4,-1.21 2.4,1.21, body extent -1.7,-0.9 1.7,0.9, height 1.35
1206_180 [mm] "1206_180"
  rect 1.1x1.6 smd: 1(-1.7,0) 2(1.7,0)
  silkscreen extent -0.9,-1 0.9,1, body extent -1.75,-0.95 1.75,0.95, height 1.8
1206L [mm] "1206 from SM-752 data"
  rect 1.1x1.75 smd: 1(-1.35,0) 2(1.35,0)
  silkscreen extent -0.4,-0.77 0.4,0.77, body extent -1.7,-0.9 1.7,0.9, height 1.35
1210_280 [mm] "SMD, 2-Leads, Body 3.6x2.8mm, Height 2.8mm"
  rect 1.1x2.2 smd: 1(-1.65,0) 2(1.65,0)
  silkscreen extent -0.84,-1.4 0.84,1.4, body extent -1.8,-1.4 1.8,1.4, height 2.8
9080032809 [mm] "Hex Nuts: M3 X .5MM pitch DIN 934 A2 - 304 Stainless"
  body extent -2.92,-2.53 2.92,2.53, height 5.29
64900829522 [mm] "4.20mm Male Dual Row Angled Header, 8p"
  rect 2.7x2.7 hole 1.8: 1(6.3,7.5)
  round 2.7 hole 1.8: 2(2.1,7.5) 3(-2.1,7.5) 4(-6.3,7.5) 5(6.3,13) 6(2.1,13) 7(-2.1,13) 8(-6.3,13)
  silkscreen extent -9.2,-6.5 9.2,7.7, body extent -9,-6.4 9.32,13.57, height 11.43
691312410003 [mm] "7.62 mm -Open Horizontal PCB Header - 03p"
  rect 2.4x2.4 hole 1.5: 1(-7.62,4)
  round 2.4 hole 1.5: 2(0,4) 3(7.62,4)
  silkscreen extent -10.52,-6 10.52,6, body extent -10.52,-6 10.52,6, height 8.55
"APM_RM3X8MM 2701" [mm] "Screw, Dia 6.7mm, Length 8mm, TH"
  body extent -3.35,-3.35 3.35,3.35, height 2.38
B32652_1800x700x1250 [mm] "TH, 2-Leads, Body 18x7mm, Pin Spacing 15mm"
  round 1.55 hole 1.05: 1(-7.5,0) 2(7.5,0)
  silkscreen extent -9,-3.5 9,3.5, body extent -9,-3.5 9,3.5, height 12.5
BuildingFastener_MPMS_003_0005_PH [mil] "MACHINE SCREW PAN PHILLIPS M3"
  round 1 on Mech3: 0(0,0)
  body extent -118,-118 118,118, height 289
BXW_1250X5000_HORIZONTAL_DOWN [mm] "TH, 2-Leads, Dia 12.5mm, Pin Spacing 5mm"
  rect 1.35x1.35 hole 0.85: 1(-2.5,2.3)
  round 1.35 hole 0.85: 2(2.5,2.3)
  silkscreen extent -6.48,-52.69 6.52,3.05, body extent -6.49,-47.41 6.49,2.54, height 13
CAPRR2250W80L2550T850H1750 [mm] "PANASONIC"
  round 1.8 hole 1.2: 1(-11.25,0) 2(11.25,0)
  silkscreen extent -12.75,-4.25 12.75,4.25, body extent -12.75,-4.25 12.75,4.25, height 17.5
CC45_850x500x1250#1 [mm] "TH, 2-Leads, Dia 8.5mm, Pin Spacing 5mm"
  round 1.4 hole 0.9: 1(-2.5,0) 2(2.5,0)
  silkscreen extent -4.25,-2.5 4.25,2.5, body extent -4.25,-2.5 4.25,2.5, height 12.5
CC45_850x500x1250#2 [mm] "TH, 2-Leads, Dia 8.5mm, Pin Spacing 5mm"
  round 2 hole 0.9: 1(-2.5,0) 2(2.5,0)
  silkscreen extent -4.25,-2.5 4.25,2.5, body extent -4.25,-2.5 4.25,2.5, height 12.5
CC45_850x500x1250#3 [mm] "TH, 2-Leads, Dia 8.5mm, Pin Spacing 5mm"
  round 1.8 hole 0.9: 1(-2.5,0) 2(2.5,0)
  silkscreen extent -4.25,-2.5 4.25,2.5, body extent -4.25,-2.5 4.25,2.5, height 12.5
CD45_700X600X1100 [mm] "TH, 2-Leads, Dia 7mm, Pin Spacing 10 mm"
  round 1.4 hole 0.9: 1(-5,0) 2(5,0)
  silkscreen extent -3.5,-3 3.5,3, body extent -5.34,-3.02 5.34,3.02, height 11
Chemi-Con_500x1100 [mm] "TH, 2-Leads, Dia 5mm, Lead Sapcing 2mm"
  rect 1.25x1.25 hole 0.75: 1(-1,0)
  round 1.25 hole 0.75: 2(1,0)
  silkscreen extent -2.8,-2.8 2.8,2.8, body extent -2.75,-2.75 2.75,2.75, height 12.5
CHEMI-CON_1000X1600 [mm] "TH, 2-Leads, Dia 10mm, Pin Spacing 5mm"
  rect 1.35x1.35 hole 0.85: 1(-2.5,0)
  round 1.35 hole 0.85: 2(2.5,0)
  silkscreen extent -5.25,-5.25 5.25,5.25, body extent -5.25,-5.25 5.26,5.25, height 17.5
CONN_923345-06-C#1 [mil] "3M, Wire jumper, 600 mil lenght, Blue"
  round 60 hole 37: 1(-300,0) 2(300,0)
  body extent -313,-35 314,35, height 70
CONN_923345-06-C#2 [mil] "3M, Wire jumper, 600 mil lenght, Blue"
  round 80 hole 40: 1(-300,0) 2(300,0)
  body extent -313,-35 314,35, height 70
DBV0006A_N [mm] "SOT23, 6-Leads, Body 2.9x1.6mm, Pitch 0.95mm, Lead Span 2.8mm, IPC Medium Density"
  rrect17% 1.2x0.6 smd: 1(-1.375,0.95) 2(-1.375,0) 3(-1.375,-0.95) 4(1.375,-0.95) 5(1.375,0) 6(1.375,0.95)
  silkscreen extent -1.68,-1.55 0.5,1.55, body extent -1.42,-1.46 1.42,1.46, height 1.12
DBZ0003A_N [mm] "SOT23, 3-Leads, Body 2.9x1.3mm, Pitch 0.95mm, Lead Span 2.4mm, IPC Medium Density"
  rrect17% 1x0.6 smd: 1(-1.2,0.95) 2(-1.2,-0.95) 3(1.2,0)
  silkscreen extent -1.65,-1.5 0.7,1.5, body extent -1.26,-1.46 1.26,1.46, height 0.98
DDB0014A [mm] "SMD, 14-Leads, Body 3.9x9.9mm, Pitch 1.27mm"
  rrect17% 2x0.6 smd: 1(-2.7,4.445) 3(-2.7,1.905) 4(-2.7,0.635) 5(-2.7,-0.635) 6(-2.7,-1.905) 7(-2.7,-3.175) 8(-2.7,-4.445) 9(2.7,-4.445) 10(2.7,-3.175) 11(2.7,-1.905) 12(2.7,-0.635) 14(2.7,1.905) 15(2.7,3.175) 16(2.7,4.445)
  silkscreen extent -3.5,-5 2,5, body extent -3.01,-4.95 3.01,4.95, height 1.75
DE_800x1200x800 [mm] "Murata"
  round 1.45 hole 0.85 paste+0 mask+0.05: 1(-5,0) 2(5,0)
  silkscreen extent -4,-4 4,4, body extent -5.3,-4 5.3,4, height 11.99
DIP4-P-10.0-2.54 [mm]
  rrect50% 1.8x1.8 hole 0.8: 1(-5.08,1.27)
  round 1.8 hole 0.8: 2(-5.08,-1.27) 3(5.08,-1.27) 4(5.08,1.27)
  silkscreen extent -7,-2.33 3.7,2.54, body extent -5.29,-2.29 5.29,2.54, height 5.59
DO-41_15mm [mm] "diode"
  rect 1.75x1.75 hole 1.15: 1(-7.5,0)
  round 1.75 hole 1.15: 2(7.5,0)
  silkscreen extent -2.62,-1.37 2.59,1.35, body extent -7.93,-1.36 7.93,1.36, height 2.72
DPAK [mm] "D-PAK, 3-Pads, Body 6.22x6.73mm (max), TO-252AA using nominal STEP model"
  rrect6% 2.6x1.6 smd: 1(-3.4,2.28) 3(-3.4,-2.28)
  rrect2% 6.2x5.8 smd paste-3: 2(3.4,0)
  body extent -3.86,-3.29 5.84,3.29, height 2.48
ECQE_2570x820x1720 [mm] "PANASONIC"
  round 1.8 hole 1.2: 1(-11.25,0) 2(11.25,0)
  silkscreen extent -12.85,-4.1 12.85,4.1, body extent -12.85,-4.1 12.85,4.1, height 17.2
EE49-8-20 [mm]
  rrect5% 3.2x3.2 hole 2 paste-1000 mask+0: 4(-28.25,3)
  round 3.2 hole 2 paste-1000 mask+0: 5(-28.25,10) 6(-28.25,16) 7(37.25,21.5) 8(37.25,15.5) 9(37.25,9.5) 10(37.25,3.5) 11(37.25,-3.5) 12(37.25,-9.5) 13(37.25,-15.5) 14(37.25,-21.5) 15(-28.25,-16) 16(-28.25,-10) 17(-28.25,-3)
  silkscreen extent -32.85,-26.25 32.85,26.25, body extent -32.95,-26.35 38.45,26.35, height 0.25
FCC_disclaimer [mm]
Fiducial10-20 [mm]
  round 1 smd mask+0.5: 1(0,0)
  Top Layer keep-out circle w1.178: c0,0 r0.5
FP-923345-08-C_JUMPER2-MFG [mm]
  rrect8% 1.3x1.3 hole 0.8 paste-1000 mask+0: 1(-10.16,0)
  round 1.3 hole 0.8 paste-1000 mask+0: 2(10.16,0)
  silkscreen extent -9.14,-0.76 9.14,0.76, body extent -10.91,-0.86 10.91,0.86, height 0.25
FP-KBJ608G_BENT [mm]
  rrect4% 3.5x2.35 hole 1.55 paste-1000 mask+0: 1(-14,11.25)
  oval 3.5x2.35 hole 1.55 paste-1000 mask+0: 2(-14,3.75) 3(-14,-3.75) 4(-14,-11.25)
  silkscreen extent -16.13,-12.6 7.65,12.6, body extent -14.48,-12.5 7.37,12.5, height 4.8
FUSE_215 [mm] "TH, Dia 5.8mm, Lead Spacing 26.4mm"
  round 2 hole 1.2: 1(-13.2,0) 2(13.2,0)
  silkscreen extent -12.15,-2.9 12.15,2.9, body extent -13.52,-2.89 13.53,2.89, height 7.29
"GND CONNECT" [mm] "GND CONNECT"
  oval 2x5.5 hole 1.1 slot 3.2 at 90 deg: 1(12,0)
  oval 1.1x2 hole 1.1 slot 2 at 90 deg: 2(8.25,0.15)
  silkscreen extent -3.5,-3.5 12,3.5
IEC_HighVoltage_Medium [mm]
  silkscreen extent -5.51,-4.46 5.51,5.09
IEC_HotSurface_Medium [mm]
  silkscreen extent -5.51,-4.76 5.51,4.78
JLB20213 [mm]
  rrect6% 2.3x2.3 hole 1.3 paste-1000 mask+0: 1(-10,8.5)
  round 2.3 hole 1.3 paste-1000 mask+0: 2(-10,-8.5) 3(10,-8.5) 4(10,8.5)
  silkscreen extent -13.48,-11.75 12.75,11.75, body extent -12.85,-11.85 12.85,11.85, height 0.25
JLC42178 [mm]
  rrect50% 2.8x3 hole 1.8 paste-1000 mask+0: 1(-19.5,-7.5) 2(-19.5,-12.58)
  oval 2.8x3 hole 1.8 paste-1000 mask+0: 3(-19.5,7.5) 4(19.5,6) 6(19.5,-6)
  silkscreen extent -21.37,-20.75 19.75,20.75, body extent -20.7,-20.85 20.7,20.85, height 0.25
Keystone5010 [mil] "Keystone Multipurpose loops"
  round 87 hole 63: 1(0,0)
  silkscreen extent -70,-70 70,70, body extent -63,-63 63,62, height 319
Keystone5011 [mil] "Keystone Multipurpose loops"
  round 87 hole 63: 1(0,0)
  silkscreen extent -70,-70 70,70, body extent -63,-63 63,62, height 319
KEYSTONE_1903C [mil] "HEX NYLON STANDOFF 6-32, F-F 0.5\""
  round 1 on Mech4: 0(0,0)
  body extent -144,-125 144,125, height 501
KEYSTONE_4820 [mm] "HEX NYLON STANDOFF 6-32, M-F 1\""
  round 0.025 on Mech3: 0(0,0)
  round 1 hole 3.6 unplated: MH(0,0)
  silkscreen extent -3.67,-3.67 3.67,3.67, body extent -3.67,-3.17 3.67,3.18, height 25.42
MPK_1800x950 [mm] "TH, 2-Leads, Body 18x9.5mm, Lead Spacing 15mm"
  round 1.8 hole 1.2: 1(-7.5,0) 2(7.5,0)
  body extent -9,-4.75 9,4.75, height 14
PR02 [mm] "Vishay-BC Components"
  round 1.6 hole 1.1: 1(-7.6,0) 2(7.6,0)
  silkscreen extent -6.42,-2 6.42,2, body extent -8.02,-2 8.02,2, height 4
"S237 - Horizontal_Down"#1 [mm] "EPCOS"
  round 2 hole 1.2: 1(-3.75,0) 2(3.75,0)
  silkscreen extent -7.5,1.25 7.5,18.5, body extent -7.5,-0.42 7.5,18.5, height 7
"S237 - Horizontal_Down"#2 [mm] "EPCOS"
  round 2.5 hole 1.2: 1(-3.75,0) 2(3.75,0)
  silkscreen extent -7.5,1.25 7.5,18.5, body extent -7.5,-0.42 7.5,18.5, height 7
SK-443-AL-75 [mm]
  oval 2x5 hole 1 slot 3.5 at 90 deg: 1(-1.25,24) 2(76.25,24)
  round 6.8 hole 3.3: 1(35,12.5) ""(15,12.5) ""(55,12.5)
  silkscreen extent 0,0 75,30.1, body extent 0,0 75,30.1, height 12.45
SK-443-AL-100 [mm]
  round 6.8 hole 3.1: 1(70,12.5) 2(20,12.5)
  oval 2x5 hole 1 slot 3.5 at 90 deg: ""(-1.25,24) ""(101.25,24)
  silkscreen extent 0,0 100,30.1, body extent 0,0 100,30.1, height 12.45
SMA [mm] "Molded Diode, 2-Leads, Body 4.3x2.6mm, IPC Medium Density, based on OnSemi component dimensions and land pattern"
  rect 2x2 smd: 1(-2,0) 2(2,0)
  silkscreen extent -3.66,-1.57 2.79,1.57, body extent -2.6,-1.3 2.6,1.3, height 2.42
SMAF [mm] "SMD, 2-Leads, Body 3.8x2.5mm"
  rect 1.24x1.89 smd: 1(-2.04,0) 2(2.04,0)
  silkscreen extent -3.4,-1.3 2.8,1.3, body extent -2.35,-1.25 2.35,1.25, height 1
SMC [mil] "Molded Diode, 2-Leads, Body 6.9x5.8mm, IPC Medium Density, based on OnSemi component dimensions and land patterns"
  rect 110x150 smd: 1(-140.49,0) 2(140.49,0)
  silkscreen extent -221,-123 189,124, body extent -156,-116 156,116, height 91
SOD-123 [mm] "On Semi recommended land pattern"
  rect 0.915x1.22 smd: 1(-1.637,0) 2(1.637,0)
  silkscreen extent -2.74,-1.17 2.03,1.17, body extent -1.93,-0.9 1.93,0.9, height 1.35
SOD-123F [mm] "NXP recommended land pattern"
  rect 1.2x1.2 smd paste-0.05: 1(-1.4,0) 2(1.4,0)
  silkscreen extent -2.64,-1.12 2.01,1.12, body extent -1.8,-0.85 1.8,0.85, height 1.2
SOD-123W [mm] "NXP recommended land pattern"
  rect 1.6x1.8 smd paste-0.05: 1(-1.4,0) 2(1.908,0)
  silkscreen extent -2.64,-1.14 1.68,1.14, body extent -1.85,-0.95 1.85,0.95, height 1.1
SOT-23 [mm] "SOT23, 3-Leads, Body 2.9x1.3mm, Pitch 0.95mm, Lead Span 2.5mm, IPC Medium Density"
  rrect50% 1x0.6 smd: 1(-1.2,0.95) 2(-1.2,-0.95) 3(1.2,0)
  silkscreen extent -1.62,-1.5 0.7,1.5, body extent -1.16,-1.45 1.21,1.45, height 1
SOT-89-3 [mm] "SOT, 3-Leads, Body 4.6 x 2.6 mm, Pitch 1.5mm"
  rect 1.4x0.9 smd: 1(-1.9,1.5) 3(-1.9,-1.5)
  rect 1.8x0.9 smd: 2(-1.7,0)
  oct 3.4x1.9 smd: 4(0.9,0)
  silkscreen extent -1.3,-2.45 1.33,2.45, body extent -2.42,-2.28 1.83,2.32, height 1.62
SOT-223 [mm] "SOT223/SC73, 4-Leads, Body 6.5x3.5mm, Pitch 2.3mm, Lead Span 7mm, IPC Medium Density"
  rrect10% 2.4x1 smd: 1(-2.9,2.3) 2(-2.9,0) 3(-2.9,-2.3)
  rrect4% 2.4x3.3 smd: 4(2.9,0)
  silkscreen extent -3.32,-3.35 1.4,3.35, body extent -3.5,-3.25 3.5,3.25, height 1.62
TO-220FP_HORIZONTAL_100MIL_STANDOFF2300 [mm] "TH, 3-Leads, Body 10.4x16mm"
  rrect50% 2x2 hole 1.3: 1(-2.54,0)
  round 2 hole 1.3: 2(0,-2.54) 3(2.54,0)
  silkscreen extent -5.1,5.6 5.1,22.2, body extent -5.09,-2.79 5.09,22.2, height 7.02
TO-220FP_Horizontal_100mil_Standoff2300 [mm] "TH, 3-Leads, Body 10.4x16mm"
  rrect50% 1.8x1.8 hole 1.3: 1(-2.54,0)
  round 1.8 hole 1.3: 2(0,-2.54) 3(2.54,0)
  silkscreen extent -5.1,5.6 5.1,22.2, body extent -5.09,-2.79 5.09,22.2, height 7.02
VR_1000x1250 [mm] "Nichicon"
  rect 1.5x1.5 hole 0.85: 1(-2.5,0)
  round 1.5 hole 0.85: 2(2.5,0)
  silkscreen extent -5.25,-5.25 5.25,5.25, body extent -5.21,-5.24 5.24,5.24, height 14.01
WEEE_Minimum [mm] "WEEElie bin"
  silkscreen extent -2.42,-4.38 2.52,2.65

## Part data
C100 C103: library part ECQ-U2A474ML, "CAP, Film, 0.47 µF, 275 V,+/- 20%, TH", Case/Package=Radial, Dielectric=PP, Manufacturer=Panasonic, Max Operating Temperature=110°C, Min Operating Temperature=-40°C, Package Quantity=100, Supplier Part Number 1=667-ECQ-UAAF474M, Tolerance_%=20%, Voltage=275V
C101 C102 C104 C105: "CAP, CERM, 1000 pF, X1 440 VAC/Y1 400 VAC, +/- 20%, E, D7xT6mm", Cap_Case=7x6x11mm, Manufacturer=TDK, Supplier Part Number 1=445-174535-ND, TempCo=E, Tolerance_%=20, ValueDisplayed=1000pF
C106 C107 C114: "CAP, CERM, 220 pF, 1000 V,+/- 5%, SL, D8.5xT5mm", Cap_Case=8.5x5x12.5mm, Manufacturer=TDK, Supplier Part Number 1=445-15974-ND, TempCo=SL, Tolerance_%=5, Value2=1000V, ValueDisplayed=220pF
C108: "CAP, Film, 1.5 µF, 450 V,+/- 10%, TH", Manufacturer=Panasonic, Supplier Part Number 1=E6828-ND, Tolerance_%=10, Value2=450V, ValueDisplayed=1.5µF
C108: library part 450MPK105J, "CAP, Film, 1 µF, 450 V,+/- 5%, TH", Cap_Case=18x9.5mm, Manufacturer=Rubycon, Supplier Part Number 1=1189-1822-ND, Tolerance_%=5, Value2=450V, ValueDisplayed=1µF
C109 C110: "CAP, AL, 68 µF, 450 V, +/- 20%, TH", Cap_Case=12.5X45mm, Manufacturer=Rubycon, Supplier Part Number 1=1189-1364-ND, Tolerance_%=20, Value1=Unknown, Value2=450V, ValueDisplayed=68µF
C111: "CAP, CERM, 10 pF, 1000 V,+/- 5%, C0G/NP0, 1206", Cap_Case=1206, Manufacturer=Vishay-Vitramon, Supplier Part Number 1=720-1010-1-ND, TempCo=C0G/NP0, Tolerance_%=5, Value2=1000V, ValueDisplayed=10pF
C112: "CAP, CERM, 3300 pF, 50 V,+/- 5%, C0G/NP0, 0805", Cap_Case=0805, Manufacturer=MuRata, Supplier Part Number 1=490-1632-1-ND, TempCo=C0G/NP0, Tolerance_%=5, Value2=50V, ValueDisplayed=3300pF
C113: "CAP, CERM, 470 pF, 50 V,+/- 5%, C0G/NP0, 0805", Cap_Case=0805, Manufacturer=AVX, Supplier Part Number 1=478-1324-1-ND, TempCo=C0G/NP0, Tolerance_%=5, Value1="0.159 ohm", Value2=50V, ValueDisplayed=470pF
C115: "CAP, CERM, 0.18 µF, 25 V,+/- 10%, X7R, 0805", Cap_Case=0805, Manufacturer=MuRata, Supplier Part Number 1=81-GRM21BR71E184KA1L, TempCo=X7R, Tolerance_%=10, Value2=25V, ValueDisplayed=0.18µF
C116: "CAP, CERM, 0.047 µF, 25 V,+/- 10%, X7R, 0805", Cap_Case=0805, Manufacturer=MuRata, Supplier Part Number 1=81-GRM40X473K25D, TempCo=X7R, Tolerance_%=10, Value2=25V, ValueDisplayed=0.047µF
C117: "CAP, CERM, 0.47 µF, 50 V,+/- 10%, X7R, 0805", Cap_Case=0805, Manufacturer=MuRata, Supplier Part Number 1=490-3328-1-ND, TempCo=X7R, Tolerance_%=10, Value2=50V, ValueDisplayed=0.47µF
C118: "CAP, CERM, 10 pF, 50 V, +/- 5%, C0G/NP0, 0805", Cap_Case=0805, Manufacturer=AVX, Supplier Part Number 1=478-1304-1-ND, TempCo=C0G/NP0, Tolerance_%=5, Value1="1.561 ohm", Value2=50V, ValueDisplayed=10pF
C119: "CAP, CERM, 2200 pF, 50 V,+/- 5%, C0G/NP0, 0805", Cap_Case=0805, Manufacturer=MuRata, Supplier Part Number 1=490-1628-1-ND, TempCo=C0G/NP0, Tolerance_%=5, Value2=50V, ValueDisplayed=2200pF
C120: "CAP, CERM, 10 µF, 25 V, +/- 10%, X7R, 0805", Cap_Case=0805, Manufacturer=MuRata, Supplier Part Number 1=81-GRM21BZ71E106KE5L, TempCo=X7R, Tolerance_%=10, Value1=Unknown, Value2=25V, ValueDisplayed=10µF
C200: "CAP, CERM, 0.1 µF, 630 V,+/- 10%, X7R, 1210", Cap_Case=1210, Manufacturer=Kemet, Supplier Part Number 1=399-13490-1-ND, TempCo=X7R, Tolerance_%=10, Value2=630V, ValueDisplayed=0.1µF
C201 C202: "CAP, CERM, 220 pF, 1000 V,+/- 5%, SL, D8.5xT5mm", Cap_Case=8.5x5x12.5mm, Manufacturer=TDK, Supplier Part Number 1=445-15974-ND, TempCo=SL, Tolerance_%=5, Value2=1kV, ValueDisplayed=220pF
C203 C204: library part B32652A7153J000, "CAP FILM 0.015UF 5% 1KVDC RADIAL", Case/Package=Radial, Dielectric Material=PP, Manufacturer="TDK EPCOS", Max Operating Temperature=100°C, Min Operating Temperature=-55°C, Supplier Part Number 1=871-B32642B0153J, Tolerance_%=5%, Voltage Rating (AC)=600V, Voltage Rating (DC)=1kV
C205: "CAP, CERM, 150 pF, 630 V,+/- 5%, C0G/NP0, 1206", Cap_Case=1206, Manufacturer=MuRata, Supplier Part Number 1=490-5274-1-ND, TempCo=C0G/NP0, Tolerance_%=5, Value2=630V, ValueDisplayed=150pF
C206: "CAP, CERM, 68 pF, 500 V,+/- 5%, C0G/NP0, 1206", Cap_Case=1206, Manufacturer=AVX, Supplier Part Number 1=12067A680JAT2A-ND, TempCo=C0G/NP0, Tolerance_%=5, Value2=500V, ValueDisplayed=68pF
C207: "CAP, CERM, 8200 pF, 50 V,+/- 5%, C0G/NP0, 1206", Cap_Case=1206, Manufacturer=MuRata, Supplier Part Number 1=490-1753-1-ND, TempCo=C0G/NP0, Tolerance_%=5, Value2=50V, ValueDisplayed=8200pF
C208: "CAP, AL, 22 µF, 50 V, +/- 20%, TH", Cap_Case=5x11, Manufacturer=Chemi-Con, Supplier Part Number 1=565-1703-ND, Tolerance_%=20, Value2=50V, ValueDisplayed=22µF
C209 C210: "CAP, CERM, 0.1 µF, 50 V, +/- 5%, X7R, 0805", Cap_Case=0805, Manufacturer=AVX, Supplier Part Number 1=478-3352-1-ND, TempCo=X7R, Tolerance_%=5, Value1="0.024 ohm", Value2=50V, ValueDisplayed=0.1µF
C211: "CAP, AL, 330 µF, 35 V, +/- 20%, TH", Cap_Case=10x12.5, Manufacturer=Nichicon, Supplier Part Number 1=493-5929-1-ND, Tolerance_%=20, Value2=35V, ValueDisplayed=330µF
C212: "CAP, CERM, 2.2 µF, 100 V,+/- 10%, X7S, 1206", Cap_Case=1206, Manufacturer=TDK, Supplier Part Number 1=445-5207-1-ND, TempCo=X7S, Tolerance_%=10, Value1="0.005718 ohm", Value2=100V, ValueDisplayed=2.2µF
C213: "CAP, CERM, 0.068 µF, 100 V,+/- 10%, X7R, 0805", Cap_Case=0805, Manufacturer=Kemet, Supplier Part Number 1=399-3484-1-ND, TempCo=X7R, Tolerance_%=10, Value1="0.078 ohm", Value2=100V, ValueDisplayed=0.068µF
C214 C215: "CAP, CERM, 4.7 µF, 25 V,+/- 10%, X7R, 0805", Cap_Case=0805, Manufacturer=MuRata, Supplier Part Number 1=490-9962-1-ND, TempCo=X7R, Tolerance_%=10, Value2=25V, ValueDisplayed=4.7µF
C216: "CAP, CERM, 100 pF, 50 V,+/- 5%, C0G/NP0, 0805", Cap_Case=0805, Manufacturer=MuRata, Supplier Part Number 1=490-1615-1-ND, TempCo=C0G/NP0, Tolerance_%=5, Value2=50V, ValueDisplayed=100pF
